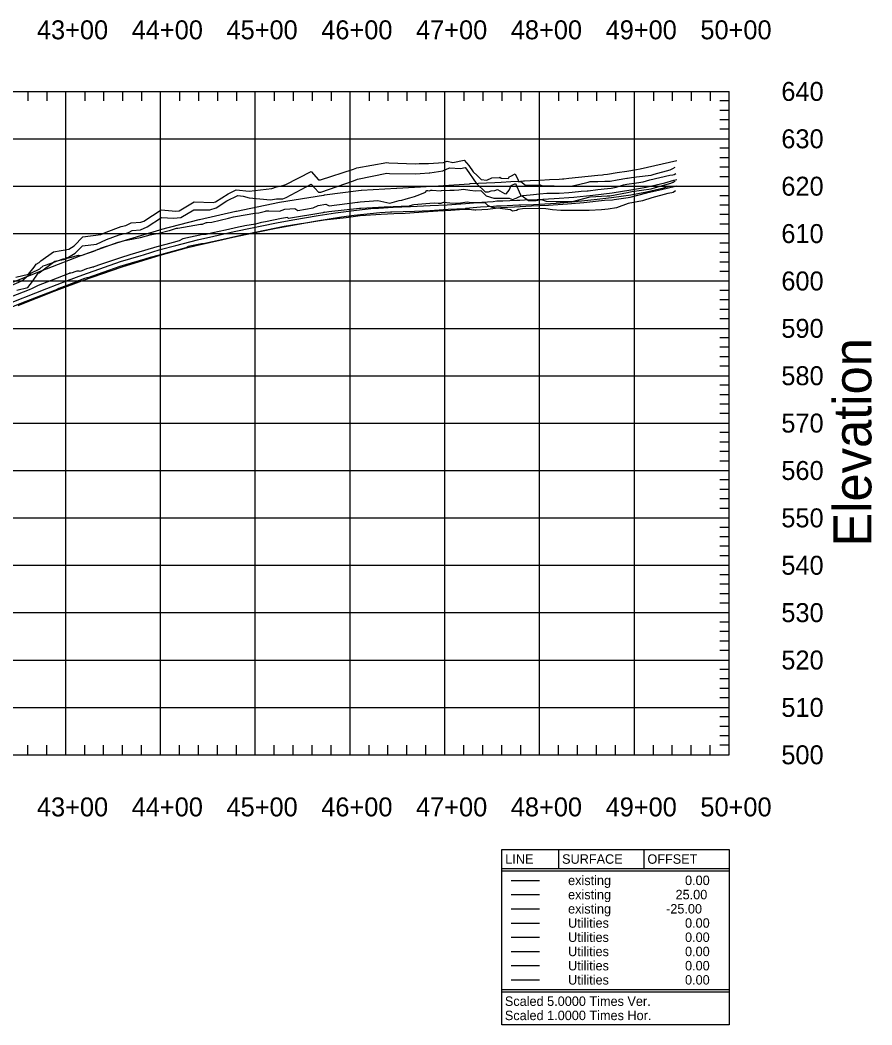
# Model space of a CAD drawing. Extents: x 704797 to 712284, y 374940 to 376945.
# Drawn here: x 711386 to 712284, y 374940 to 376001 of the extents above; entities that cross this region are included whole.
import ezdxf

# ---------------------------------------------------------------- set-up
doc = ezdxf.new("R2010")
doc.units = 0
for name, color, linetype in [('1', 7, 'Continuous'), ('10', 7, 'Continuous'), ('12', 7, 'Continuous'), ('13', 7, 'Continuous'), ('61', 7, 'Continuous'), ('63', 7, 'Continuous'), ('Default_Profile', 7, 'Continuous'), ('Existing', 7, 'Continuous')]:
    doc.layers.add(name, color=color, linetype=linetype)

msp = doc.modelspace()

# ---------------------------------------------------------------- linework, layer by layer
at = {"layer": '10'}
for points in [[(711382.1, 375715.8), (711393.6, 375718.6), (711398.8, 375725.1), (711404.5, 375733.6), (711405.1, 375733.9), (711405.5, 375734.2), (711422.3, 375746.3), (711433.2, 375748.4), (711443.7, 375755), (711451.3, 375762.5), (711466.2, 375764.4), (711476.8, 375769.4), (711490, 375774.3), (711499, 375776.4), (711500.5, 375777.1), (711503.9, 375778.9), (711512.6, 375779.6), (711519.6, 375782.5), (711534.7, 375792.6), (711547.4, 375791.6), (711555.3, 375792.4), (711568.9, 375800.5), (711585.7, 375800.4), (711592.4, 375802.5), (711603.6, 375809.9), (711615.3, 375815.6), (711621, 375815.1), (711627.2, 375813.3), (711649.8, 375811), (711656.1, 375812), (711661.6, 375812), (711662.8, 375812.3), (711666.1, 375813.4), (711692.7, 375827.6), (711700.3, 375819.2), (711702.9, 375819.3), (711737.3, 375831.3), (711741.6, 375832.9), (711772.5, 375839.3), (711775.4, 375838.9), (711802.2, 375838.5), (711807.6, 375839), (711817.1, 375839.5), (711817.9, 375839.6), (711831.7, 375841.6), (711838.5, 375845), (711850.3, 375844), (711855.1, 375845.2), (711856.7, 375843.5), (711866.9, 375828.6), (711867.6, 375828.1), (711876.3, 375819.6), (711879.7, 375819.4), (711882.5, 375820.6), (711886.5, 375820.9), (711889.3, 375821.9), (711896.6, 375817.7), (711898.6, 375817.5), (711898.9, 375817.9), (711901.5, 375821.3), (711903.6, 375826.2), (711908.1, 375828.2), (711913.6, 375816.3), (711913.9, 375815.3), (711915.3, 375815.5), (711921.8, 375810.5), (711930.2, 375810.5), (711935.7, 375811.5), (711940.5, 375809.6), (711950.9, 375809.3), (711962, 375809.3), (711964, 375809.3), (711968.4, 375809.3), (711986.9, 375814.4), (712005.1, 375815.4), (712007.6, 375815.5), (712026.4, 375819), (712030.9, 375820), (712051.4, 375822.8), (712055.9, 375824.1), (712072, 375828.6), (712074.5, 375829.8), (712076.8, 375831.1)], [(712076.9, 375820.5), (712074.6, 375818.7), (712073.1, 375818.4), (712068.8, 375817.9), (712052.1, 375813.2), (712042.4, 375810.2), (712027.2, 375807.4), (712014.9, 375802.8), (712005.9, 375801.3), (711999, 375800.6), (711985.9, 375799.7), (711975.8, 375799.8), (711955.9, 375799.8), (711947.1, 375800.7), (711940.3, 375801.5), (711932.2, 375801.8), (711915.7, 375801.6), (711911.1, 375800.8), (711909.3, 375799.9), (711905.2, 375799.2), (711902.8, 375800.4), (711883.6, 375803), (711879, 375805), (711876.3, 375808.1), (711861.7, 375808.1), (711859.5, 375808.4), (711857.3, 375808.7), (711847.7, 375807.4), (711845.1, 375807.3), (711838.8, 375807.5), (711832.4, 375808.2), (711831.9, 375808.2), (711829.4, 375807.2), (711828.2, 375807.4), (711826.6, 375807.4), (711822.5, 375807.6), (711817.9, 375807.3), (711801, 375806), (711799.3, 375805.4), (711799.1, 375805.4), (711797.2, 375804.8), (711796.7, 375804.7), (711796.1, 375804.5), (711779.3, 375803.7), (711777.8, 375803.3), (711775.9, 375803.7), (711745.2, 375802.1), (711743.7, 375801.9), (711711.2, 375798.3), (711707.1, 375797.7), (711706.2, 375798.1), (711704.8, 375797.4), (711668.9, 375791.5), (711667.6, 375792.3), (711661.3, 375791.4), (711644.6, 375788), (711640.3, 375787.1), (711639, 375786.7), (711633.8, 375785.5), (711622.8, 375783.7), (711621.3, 375783.4), (711616.1, 375782.3), (711602.3, 375779.2), (711588.8, 375776.2), (711583.1, 375774.9), (711581.9, 375774.6), (711578.4, 375774.4), (711557.3, 375770.1), (711553.5, 375767.9), (711547.1, 375766.2), (711539.3, 375764.1), (711529.7, 375761.4), (711507.4, 375754.8), (711501.4, 375753), (711491.5, 375750), (711470.3, 375742.7), (711463.4, 375740.3), (711463, 375740.1), (711462.4, 375740), (711461.9, 375739.9), (711458.5, 375739.1), (711455.5, 375738.3), (711450.7, 375736.1), (711449.7, 375735.9), (711448, 375735.5), (711447.9, 375735.6), (711447.7, 375736), (711446.6, 375735.9), (711445.4, 375735.7), (711443.4, 375735.1), (711440.4, 375734.1), (711439.1, 375733.8), (711438.3, 375733.6), (711437.8, 375733.6), (711437.4, 375733.5), (711418.4, 375726), (711404.6, 375720.7), (711398.3, 375717.6), (711395.1, 375716.3), (711376, 375708.7)]]:
    msp.add_lwpolyline(points, dxfattribs=at)
at = {"layer": '12'}
for points in [[(711377, 375703.2), (711402.2, 375713), (711413.6, 375717.6), (711435.5, 375726), (711451.7, 375732), (711474.7, 375740.1), (711491.5, 375745.9), (711513.2, 375752.4), (711515.8, 375753.2), (711533.2, 375758.6), (711549.7, 375763), (711572.6, 375768.9), (711589.8, 375772.7), (711611.3, 375777.6), (711630.4, 375781.5), (711640.6, 375783.7), (711655.9, 375786.9), (711673.4, 375790.1), (711699.9, 375794.5), (711718.2, 375797.5), (711740.6, 375800.3), (711758.9, 375802.2), (711763.6, 375802.4), (711779.1, 375803.4), (711797.5, 375803.9), (711818.2, 375805), (711836.3, 375806), (711855.4, 375807.1), (711855.6, 375807.2), (711872.6, 375808.7), (711884.7, 375809.3), (711888.4, 375809.9), (711894.9, 375810), (711909.7, 375810.7), (711912.8, 375810.8), (711917.9, 375811), (711931, 375811.4), (711949, 375812.4), (711969.8, 375814), (711989.9, 375816.1), (712010.2, 375818.4), (712029.8, 375821.5), (712046.1, 375824.6), (712065.9, 375829.1), (712075.3, 375831.7), (712078.6, 375832.5)], [(711383.6, 375699.7), (711391.2, 375702.7), (711414.6, 375712), (711421.4, 375714.6), (711453.5, 375726.7), (711461.6, 375729.5), (711493.3, 375740.5), (711502.3, 375743.2), (711533.2, 375752.8), (711561, 375760.3), (711571.4, 375763), (711599.3, 375769.3), (711610.1, 375771.7), (711640.2, 375778), (711654, 375780.9), (711681.2, 375785.9), (711696.5, 375788.5), (711724.5, 375793.1), (711738.1, 375794.8), (711765.1, 375797.6), (711776.3, 375798.3), (711777.7, 375798.3), (711801.6, 375799), (711817.7, 375799.9), (711837.1, 375801.1), (711855.6, 375802.1), (711855.8, 375802.3), (711871.2, 375803.7), (711885, 375804.4), (711888.1, 375804.8), (711893.1, 375804.9), (711911.6, 375805.8), (711913.9, 375805.8), (711927.3, 375806.3), (711951.1, 375807.6), (711967.7, 375808.9), (711991.3, 375811.3), (712009.5, 375813.4), (712029.9, 375816.5), (712046.4, 375819.6), (712064.6, 375823.7), (712069.2, 375825)]]:
    msp.add_lwpolyline(points, dxfattribs=at)
at = {"layer": '13'}
msp.add_lwpolyline([(712078.6, 375825.5), (712077, 375825.1), (712062.3, 375821.7), (712046.3, 375818.1), (712028.7, 375813.4), (712027.2, 375813.3), (712012.2, 375811), (712010.6, 375810.9), (712002.2, 375810.5), (711980.4, 375808.1), (711963.1, 375806.4), (711943, 375805.3), (711925.2, 375804.4), (711907, 375803.2), (711892.9, 375802.5), (711881.4, 375801.2), (711879, 375800.9), (711866.5, 375800.3), (711865.3, 375800.1), (711864, 375800.4), (711863.8, 375800.3), (711859.7, 375800.8), (711859.4, 375800.8), (711853.6, 375800.8), (711840.1, 375800), (711826.4, 375799.1), (711806.3, 375797.7), (711791.9, 375796.8), (711779.8, 375796.3), (711766.5, 375795.5), (711744.5, 375794.1), (711729.6, 375792.2), (711706.3, 375789.8), (711682.5, 375785.8), (711681.6, 375785.7), (711664.3, 375782.9), (711633.5, 375776.6), (711615.2, 375772.8), (711596.6, 375768.7), (711580.3, 375765), (711579.5, 375764.8), (711577.1, 375764.7), (711562.9, 375761.8), (711560.4, 375760.3), (711542.5, 375755.7), (711530.9, 375752.5), (711522.6, 375750.1), (711517.2, 375748.6), (711496.6, 375742.4), (711490.6, 375740.6), (711478.8, 375736.6), (711457, 375728.9), (711456.7, 375728.8), (711456.4, 375728.8), (711456.1, 375728.7), (711452.4, 375727.8), (711448.1, 375726), (711447.2, 375725.5), (711446.2, 375725), (711445.1, 375724.5), (711426.4, 375717.4), (711424.5, 375716.6), (711407, 375709.9), (711387.1, 375702.1), (711365.5, 375693.4)], dxfattribs=at)
at = {"layer": '61'}
for p, q in [((708133.7, 375925.5), (712133.7, 375925.5)), ((711393.7, 375925.5), (711393.7, 375915.5)), ((711413.7, 375925.5), (711413.7, 375915.5)), ((711433.7, 375225.5), (711433.7, 375925.5)), ((711453.7, 375925.5), (711453.7, 375915.5)), ((711473.7, 375925.5), (711473.7, 375915.5)), ((711493.7, 375925.5), (711493.7, 375915.5)), ((711513.7, 375925.5), (711513.7, 375915.5)), ((711533.7, 375225.5), (711533.7, 375925.5)), ((711553.7, 375925.5), (711553.7, 375915.5)), ((711573.7, 375925.5), (711573.7, 375915.5)), ((711593.7, 375925.5), (711593.7, 375915.5)), ((711613.7, 375925.5), (711613.7, 375915.5)), ((711633.7, 375225.5), (711633.7, 375925.5)), ((711653.7, 375925.5), (711653.7, 375915.5)), ((711673.7, 375925.5), (711673.7, 375915.5)), ((711693.7, 375925.5), (711693.7, 375915.5)), ((711713.7, 375925.5), (711713.7, 375915.5)), ((711733.7, 375225.5), (711733.7, 375925.5)), ((711753.7, 375925.5), (711753.7, 375915.5)), ((711773.7, 375925.5), (711773.7, 375915.5)), ((711793.7, 375925.5), (711793.7, 375915.5)), ((711813.7, 375925.5), (711813.7, 375915.5)), ((711833.7, 375225.5), (711833.7, 375925.5)), ((711853.7, 375925.5), (711853.7, 375915.5)), ((711873.7, 375925.5), (711873.7, 375915.5)), ((711893.7, 375925.5), (711893.7, 375915.5)), ((711913.7, 375925.5), (711913.7, 375915.5)), ((711933.7, 375225.5), (711933.7, 375925.5)), ((711953.7, 375925.5), (711953.7, 375915.5)), ((711973.7, 375925.5), (711973.7, 375915.5)), ((711993.7, 375925.5), (711993.7, 375915.5)), ((712013.7, 375925.5), (712013.7, 375915.5)), ((712033.7, 375225.5), (712033.7, 375925.5)), ((712053.7, 375925.5), (712053.7, 375915.5)), ((712073.7, 375925.5), (712073.7, 375915.5)), ((712093.7, 375925.5), (712093.7, 375915.5)), ((712113.7, 375925.5), (712113.7, 375915.5)), ((712133.7, 375225.5), (712133.7, 375925.5)), ((712133.7, 375915.5), (712123.7, 375915.5)), ((712133.7, 375905.5), (712123.7, 375905.5)), ((712133.7, 375895.5), (712123.7, 375895.5)), ((712133.7, 375885.5), (712123.7, 375885.5)), ((708133.7, 375875.5), (712133.7, 375875.5)), ((712133.7, 375865.5), (712123.7, 375865.5)), ((712133.7, 375855.5), (712123.7, 375855.5)), ((712133.7, 375845.5), (712123.7, 375845.5)), ((712133.7, 375835.5), (712123.7, 375835.5)), ((708133.7, 375825.5), (712133.7, 375825.5)), ((712133.7, 375815.5), (712123.7, 375815.5)), ((712133.7, 375805.5), (712123.7, 375805.5)), ((712133.7, 375795.5), (712123.7, 375795.5)), ((712133.7, 375785.5), (712123.7, 375785.5)), ((708133.7, 375775.5), (712133.7, 375775.5)), ((712133.7, 375765.5), (712123.7, 375765.5)), ((712133.7, 375755.5), (712123.7, 375755.5)), ((712133.7, 375745.5), (712123.7, 375745.5)), ((712133.7, 375735.5), (712123.7, 375735.5)), ((708133.7, 375725.5), (712133.7, 375725.5)), ((712133.7, 375715.5), (712123.7, 375715.5)), ((712133.7, 375705.5), (712123.7, 375705.5)), ((712133.7, 375695.5), (712123.7, 375695.5)), ((712133.7, 375685.5), (712123.7, 375685.5)), ((708133.7, 375675.5), (712133.7, 375675.5)), ((712133.7, 375665.5), (712123.7, 375665.5)), ((712133.7, 375655.5), (712123.7, 375655.5)), ((712133.7, 375645.5), (712123.7, 375645.5)), ((712133.7, 375635.5), (712123.7, 375635.5)), ((708133.7, 375625.5), (712133.7, 375625.5)), ((712133.7, 375615.5), (712123.7, 375615.5)), ((712133.7, 375605.5), (712123.7, 375605.5)), ((712133.7, 375595.5), (712123.7, 375595.5)), ((712133.7, 375585.5), (712123.7, 375585.5)), ((708133.7, 375575.5), (712133.7, 375575.5)), ((712133.7, 375565.5), (712123.7, 375565.5)), ((712133.7, 375555.5), (712123.7, 375555.5)), ((712133.7, 375545.5), (712123.7, 375545.5)), ((712133.7, 375535.5), (712123.7, 375535.5)), ((708133.7, 375525.5), (712133.7, 375525.5)), ((712133.7, 375515.5), (712123.7, 375515.5)), ((712133.7, 375505.5), (712123.7, 375505.5)), ((712133.7, 375495.5), (712123.7, 375495.5)), ((712133.7, 375485.5), (712123.7, 375485.5)), ((708133.7, 375475.5), (712133.7, 375475.5)), ((712133.7, 375465.5), (712123.7, 375465.5)), ((712133.7, 375455.5), (712123.7, 375455.5)), ((712133.7, 375445.5), (712123.7, 375445.5)), ((712133.7, 375435.5), (712123.7, 375435.5)), ((708133.7, 375425.5), (712133.7, 375425.5)), ((712133.7, 375415.5), (712123.7, 375415.5)), ((712133.7, 375405.5), (712123.7, 375405.5)), ((712133.7, 375395.5), (712123.7, 375395.5)), ((712133.7, 375385.5), (712123.7, 375385.5)), ((708133.7, 375375.5), (712133.7, 375375.5)), ((712133.7, 375365.5), (712123.7, 375365.5)), ((712133.7, 375355.5), (712123.7, 375355.5)), ((712133.7, 375345.5), (712123.7, 375345.5)), ((712133.7, 375335.5), (712123.7, 375335.5)), ((708133.7, 375325.5), (712133.7, 375325.5)), ((712133.7, 375315.5), (712123.7, 375315.5)), ((712133.7, 375305.5), (712123.7, 375305.5)), ((712133.7, 375295.5), (712123.7, 375295.5)), ((712133.7, 375285.5), (712123.7, 375285.5)), ((708133.7, 375275.5), (712133.7, 375275.5)), ((712133.7, 375265.5), (712123.7, 375265.5)), ((712133.7, 375255.5), (712123.7, 375255.5)), ((712133.7, 375245.5), (712123.7, 375245.5)), ((711393.7, 375225.5), (711393.7, 375235.5)), ((711413.7, 375225.5), (711413.7, 375235.5)), ((711453.7, 375225.5), (711453.7, 375235.5)), ((711473.7, 375225.5), (711473.7, 375235.5)), ((711493.7, 375225.5), (711493.7, 375235.5)), ((711513.7, 375225.5), (711513.7, 375235.5)), ((711553.7, 375225.5), (711553.7, 375235.5)), ((711573.7, 375225.5), (711573.7, 375235.5)), ((711593.7, 375225.5), (711593.7, 375235.5)), ((711613.7, 375225.5), (711613.7, 375235.5)), ((711653.7, 375225.5), (711653.7, 375235.5)), ((711673.7, 375225.5), (711673.7, 375235.5)), ((711693.7, 375225.5), (711693.7, 375235.5)), ((711713.7, 375225.5), (711713.7, 375235.5)), ((711753.7, 375225.5), (711753.7, 375235.5)), ((711773.7, 375225.5), (711773.7, 375235.5)), ((711793.7, 375225.5), (711793.7, 375235.5)), ((711813.7, 375225.5), (711813.7, 375235.5)), ((711853.7, 375225.5), (711853.7, 375235.5)), ((711873.7, 375225.5), (711873.7, 375235.5)), ((711893.7, 375225.5), (711893.7, 375235.5)), ((711913.7, 375225.5), (711913.7, 375235.5)), ((711953.7, 375225.5), (711953.7, 375235.5)), ((711973.7, 375225.5), (711973.7, 375235.5)), ((711993.7, 375225.5), (711993.7, 375235.5)), ((712013.7, 375225.5), (712013.7, 375235.5)), ((712053.7, 375225.5), (712053.7, 375235.5)), ((712073.7, 375225.5), (712073.7, 375235.5)), ((712093.7, 375225.5), (712093.7, 375235.5)), ((712113.7, 375225.5), (712113.7, 375235.5)), ((712133.7, 375235.5), (712123.7, 375235.5)), ((708133.7, 375225.5), (712133.7, 375225.5)), ((711953.7, 375125.5), (711953.7, 375105.5)), ((712043.7, 375125.5), (712043.7, 375105.5)), ((711893.7, 375105.5), (712133.7, 375105.5)), ((711893.7, 375103), (712133.7, 375103)), ((711893.7, 374978), (712133.7, 374978)), ((711893.7, 374975.5), (712133.7, 374975.5))]:
    msp.add_line(p, q, dxfattribs=at)
msp.add_lwpolyline([(711893.7, 375125.5), (712133.7, 375125.5), (712133.7, 374940.5), (711893.7, 374940.5)], close=True, dxfattribs=at)
at = {"layer": '63'}
for p, q in [((711903.7, 375078), (711933.7, 375078)), ((711903.7, 375063), (711933.7, 375063))]:
    msp.add_line(p, q, dxfattribs=at)
for points in [[(711380.9, 375729.4), (711394.3, 375732.7), (711400.3, 375740.2), (711402.4, 375743.3), (711405.5, 375745), (711407.5, 375746.6), (711420.8, 375756.2), (711437.1, 375759.2), (711442.5, 375762.5), (711451.9, 375772), (711470.7, 375774.4), (711476.2, 375777), (711492.2, 375782.9), (711497, 375784), (711502.7, 375786.8), (711513.1, 375787.5), (711516.1, 375788.7), (711534.3, 375800.7), (711549.9, 375799.2), (711553.2, 375799.5), (711569.2, 375808.9), (711589.4, 375808.4), (711591.6, 375809), (711604.9, 375817.6), (711613.6, 375821.7), (711627.4, 375820.4), (711651, 375822.9), (711656, 375824.8), (711662.8, 375826.4), (711665.8, 375827.3), (711692.6, 375841), (711700.4, 375832.2), (711702.4, 375832.2), (711737.4, 375843.5), (711740.7, 375844.7), (711772.5, 375850.5), (711774.7, 375850.1), (711802.7, 375849), (711806.5, 375849.3), (711816.6, 375849.5), (711832.3, 375850.4), (711836.1, 375851.9), (711842.1, 375850.6), (711854.2, 375852.8), (711859.1, 375847.2), (711863.4, 375840.6), (711867.9, 375836.8), (711872, 375832.6), (711878, 375832), (711883.3, 375834.2), (711891.2, 375834.8), (711891.7, 375835), (711893.2, 375834.1), (711893.2, 375834.1), (711900.6, 375833.5), (711901.2, 375834.3), (711901.7, 375835.4), (711903.4, 375836.2), (711908, 375838.5), (711911.2, 375831.8), (711911.7, 375830.2), (711913.6, 375830.5), (711913.9, 375830.5), (711918.8, 375826.7), (711923.8, 375826.7), (711932.1, 375826.7), (711934, 375827), (711934.2, 375827), (711936.1, 375826.3), (711944.2, 375826), (711949, 375825.8), (711954.4, 375825.7), (711964.5, 375825.5), (711964.6, 375825.5), (711966.7, 375825.5), (711974.8, 375827.4), (711985, 375829.8), (711987, 375830.3), (711995.2, 375830.5), (712002.6, 375830.7), (712005.4, 375830.8), (712008.1, 375830.9), (712015.6, 375832.1), (712025.8, 375833.9), (712026.5, 375834), (712030.5, 375834.8), (712036, 375835.4), (712051.3, 375837.3), (712054.4, 375838.2), (712071.3, 375842.7), (712074.1, 375844), (712076.6, 375845.4)], [(711365.7, 375716.2), (711387.3, 375725.7), (711396.8, 375733.8), (711406.4, 375738.4), (711410, 375741.4), (711412.4, 375742.2), (711430.9, 375748.9), (711433.1, 375748.9), (711435.1, 375750.4), (711435.2, 375749.4), (711438.3, 375750.3), (711447.2, 375752.7), (711447.5, 375752.3), (711448.8, 375752.3), (711449.8, 375752.5), (711457, 375754.8), (711463.4, 375757.1), (711465.1, 375757.8), (711465.6, 375758), (711466.5, 375758.5), (711467.9, 375759), (711468, 375759), (711469.2, 375759.5), (711470.5, 375760), (711471.6, 375760.5), (711483.3, 375764.2), (711485.8, 375765.1), (711487.7, 375765.6), (711495.8, 375768.1), (711497.7, 375768.5), (711512.5, 375771.5), (711522.6, 375774.3), (711531.8, 375775.9), (711542.9, 375778.9), (711543, 375778.9), (711543, 375778.9), (711550.4, 375781.2), (711551.7, 375781.1), (711551.8, 375781.2), (711576, 375785.3), (711576.7, 375785.5), (711577.1, 375785.5), (711577.9, 375785.4), (711578.1, 375785.6), (711581.3, 375787), (711582.2, 375787.3), (711583, 375787.2), (711587.9, 375787.6), (711605.4, 375791.9), (711610.7, 375793.2), (711612.7, 375793.4), (711633.2, 375797.2), (711637.3, 375797.4), (711644.4, 375799.1), (711645.3, 375799.4), (711648, 375799.5), (711659.4, 375799), (711665, 375801.2), (711675.3, 375801.8), (711678.4, 375799.8), (711694.9, 375802.5), (711700.2, 375805.1), (711708.1, 375806.4), (711711.6, 375804.7), (711741.6, 375808.6), (711741.9, 375808.6), (711742.1, 375808.7), (711744.4, 375808.9), (711758.3, 375810.2), (711762.9, 375810.4), (711775.5, 375807.7), (711785.6, 375810.5), (711788.3, 375810.7), (711792.7, 375812.3), (711796.7, 375813.2), (711801.6, 375814.7), (711807.4, 375816.9), (711813.2, 375819.3), (711814.2, 375820.7), (711814.3, 375820.9), (711815.8, 375820.9), (711817.6, 375820.6), (711818.9, 375821.2), (711820.3, 375821.2), (711829, 375820.5), (711830.3, 375821.1), (711839.1, 375821.3), (711843.4, 375821.2), (711848.4, 375821.5), (711853.4, 375822.2), (711860.1, 375821.3), (711866.2, 375820.6), (711871.8, 375820.9), (711877.2, 375815.5), (711885.2, 375812.9), (711893.2, 375812.9), (711901.7, 375812.9), (711903.4, 375812.3), (711905.1, 375811.6), (711908.8, 375812.7), (711911, 375814), (711913.6, 375814.8), (711916.1, 375815.6), (711923.8, 375816.4), (711934, 375817.4), (711941.3, 375818), (711944.2, 375818), (711947.3, 375818), (711954, 375818), (711954.4, 375818), (711964.6, 375819), (711974.8, 375819.9), (711977.4, 375820.1), (711984, 375820.5), (711985, 375820.6), (711995.2, 375821.9), (712005.4, 375823.1), (712009, 375823.4), (712014.6, 375824.3), (712015.6, 375824.7), (712022.3, 375827), (712025.8, 375827.6), (712036, 375829.2), (712043.1, 375830.2), (712050, 375832.1), (712071.1, 375837.2), (712074.1, 375837.5), (712075.7, 375837.7), (712077.4, 375839)]]:
    msp.add_lwpolyline(points, dxfattribs=at)
at = {"layer": 'Default_Profile'}
for p, q in [((711903.7, 375048), (711933.7, 375048)), ((711903.7, 375033), (711933.7, 375033)), ((711903.7, 375018), (711933.7, 375018)), ((711903.7, 375003), (711933.7, 375003)), ((711903.7, 374988), (711933.7, 374988))]:
    msp.add_line(p, q, dxfattribs=at)
at = {"layer": 'Existing'}
msp.add_line((711903.7, 375093), (711933.7, 375093), dxfattribs=at)
msp.add_lwpolyline([(711373.3, 375722.5), (711412.4, 375738), (711413.3, 375738.3), (711449.6, 375752.2), (711449.6, 375752.2), (711449.7, 375752.3), (711449.7, 375752.3), (711449.9, 375752.4), (711450.1, 375752.4), (711450.1, 375752.4), (711450.1, 375752.4), (711450.1, 375752.4), (711489.1, 375766.3), (711489.5, 375766.4), (711489.7, 375766.4), (711516.4, 375774.6), (711532.9, 375779.5), (711533.3, 375779.6), (711533.7, 375779.7), (711574.4, 375790.2), (711575, 375790.3), (711613.3, 375799), (711613.7, 375799.1), (711659.1, 375808.6), (711705.8, 375816.2), (711706.2, 375816.2), (711706.6, 375816.3), (711745.5, 375821.2), (711745.6, 375821.2), (711782.5, 375823.5), (711782.9, 375823.5), (711820.4, 375825.7), (711821.2, 375825.7), (711821.2, 375825.7), (711859.8, 375827.9), (711860.3, 375828.2), (711860.3, 375828.2), (711886.6, 375829.5), (711886.6, 375829.5), (711886.6, 375829.5), (711893.2, 375829.8), (711903.4, 375830.3), (711913.6, 375830.9), (711916.6, 375831), (711916.7, 375831), (711917.7, 375831.1), (711923.8, 375831.4), (711934, 375831.9), (711944.2, 375832.5), (711954.4, 375833), (711957.7, 375833.2), (711959.2, 375833.3), (711964.6, 375833.9), (711974.8, 375834.9), (711985, 375836), (711995.2, 375837), (712000.1, 375837.5), (712001.4, 375837.7), (712005.4, 375838.3), (712015.6, 375839.9), (712025.8, 375841.5), (712036, 375843.1), (712039.6, 375843.7), (712078.6, 375852.5)], dxfattribs=at)

# ---------------------------------------------------------------- texts
at = {"layer": '1'}
for s, p in [(' LINE ', (711893.7, 375110.5)), (' SURFACE ', (711953.7, 375110.5)), (' OFFSET ', (712043.7, 375110.5)), ('existing', (711963.7, 375088)), ('0.00', (712087.1, 375088)), ('existing', (711963.7, 375073)), ('25.00', (712077.1, 375073)), ('existing', (711963.7, 375058)), ('-25.00', (712067.1, 375058)), ('Utilities', (711963.7, 375043)), ('0.00', (712087.1, 375043)), ('Utilities', (711963.7, 375028)), ('0.00', (712087.1, 375028)), ('Utilities', (711963.7, 375013)), ('0.00', (712087.1, 375013)), ('Utilities', (711963.7, 374998)), ('0.00', (712087.1, 374998)), ('Utilities', (711963.7, 374983)), ('0.00', (712087.1, 374983)), ('Scaled 5.0000 Times Ver.', (711897, 374960.5)), ('Scaled 1.0000 Times Hor.', (711897, 374945.5))]:
    msp.add_text(s, height=10, dxfattribs=at).set_placement(p)
at = {"layer": '61'}
for s, p in [('43+00', (711403.3, 375980.5)), ('44+00', (711503.3, 375980.5)), ('45+00', (711603.3, 375980.5)), ('46+00', (711703.3, 375980.5)), ('47+00', (711803.3, 375980.5)), ('48+00', (711903.3, 375980.5)), ('49+00', (712003.3, 375980.5)), ('50+00', (712103.3, 375980.5)), ('640', (712188.7, 375915.5)), ('640', (712188.7, 375915.5)), ('630', (712188.7, 375865.5)), ('620', (712188.7, 375815.5)), ('610', (712188.7, 375765.5)), ('600', (712188.7, 375715.5)), ('590', (712188.7, 375665.5)), ('580', (712188.7, 375615.5)), ('570', (712188.7, 375565.5)), ('560', (712188.7, 375515.5)), ('550', (712188.7, 375465.5)), ('540', (712188.7, 375415.5)), ('530', (712188.7, 375365.5)), ('520', (712188.7, 375315.5)), ('510', (712188.7, 375265.5)), ('500', (712188.7, 375215.5)), ('43+00', (711403.3, 375160.5)), ('44+00', (711503.3, 375160.5)), ('45+00', (711603.3, 375160.5)), ('46+00', (711703.3, 375160.5)), ('47+00', (711803.3, 375160.5)), ('48+00', (711903.3, 375160.5)), ('49+00', (712003.3, 375160.5)), ('50+00', (712103.3, 375160.5))]:
    msp.add_text(s, height=20, dxfattribs=at).set_placement(p)
msp.add_text('Elevation', height=40, rotation=90, dxfattribs=at).set_placement((712283.7, 375445.2))

doc.saveas('drawing.dxf')
